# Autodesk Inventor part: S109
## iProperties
Author: Administrator
Revision Number: A
Shininess: 20.0
PropertySet Name: _Private Model Information
Created: 2000-11
Part Number: S109
Project: ACME
Description: SCREW, 1/4-20 X 3/4 HEX SKT
Document SubType Name: Modeling
Standard: ANSI B18.3 - 1/4 - 20 - 3/4
Designer: E. MOSS
Control State: 0
Master: False
Checked Out: False
PropertySet Name: Design Tracking Control
Density: 0.0
Volume: 0.0
Area: 0.0
PropertySet Name: Model Information
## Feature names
1. Base1
